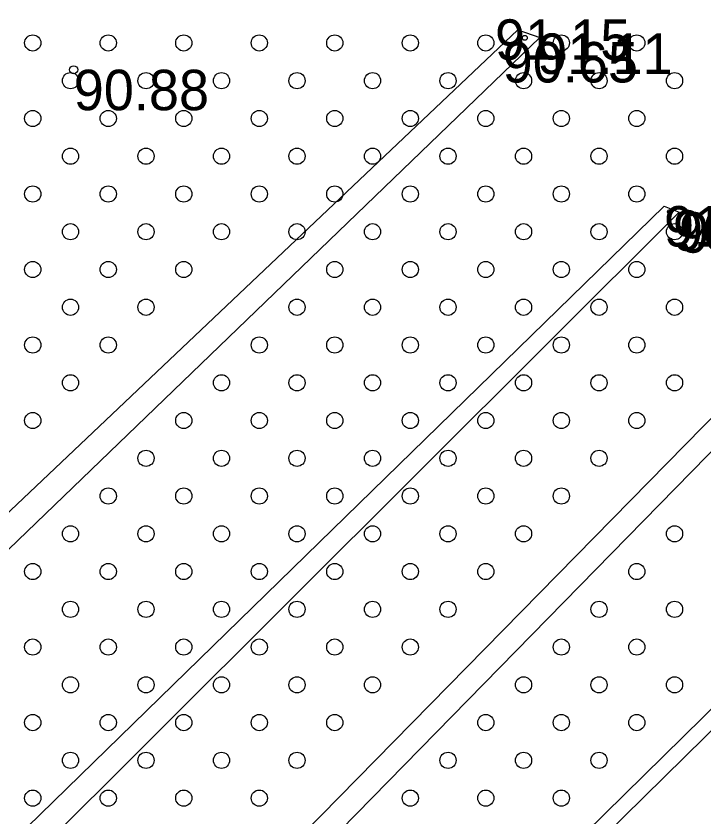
# Model space of a CAD drawing. Extents: x 316000 to 728450, y 314368 to 726000.
# Drawn here: x 725702.4 to 725766.2, y 315523.2 to 315597.5 of the extents above; entities that cross this region are included whole.
import ezdxf

# ---------------------------------------------------------------- set-up
doc = ezdxf.new("R2010")
doc.units = 0
for name, color, linetype in [('HIDG_ELEM_####_####_#', 7, 'Continuous'), ('HIDG_GRAV_####_####_#', 7, 'Continuous'), ('RELJ_AATZ_####_TKST_#', 7, 'Continuous'), ('RELJ_ELEM_####_####_#', 7, 'Continuous'), ('RELJ_NOGA_####_####_#', 7, 'Continuous'), ('TERT_ELEM_####_####_#', 7, 'Continuous')]:
    doc.layers.add(name, color=color, linetype=linetype)

msp = doc.modelspace()

# ---------------------------------------------------------------- linework, layer by layer
at = {"layer": 'HIDG_ELEM_####_####_#'}
for centre in [(725749.6236243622, 315595.47545343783), (725763.0801359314, 315579.33568528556)]:
    msp.add_circle(centre, 0.225, dxfattribs=at)
at = {"layer": 'HIDG_GRAV_####_####_#'}
for points in [[(725748.973, 315596.209), (725751.0100204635, 315595.5121681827), (725643.1476843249, 315491.6312040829), (725641.4060000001, 315494.343), (725748.973, 315596.209)], [(725762.521, 315579.879), (725763.92, 315579.31), (725655.191, 315470.892), (725652.9782202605, 315473.11112715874), (725762.521, 315579.879)], [(725774.6040000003, 315568.073), (725776.896, 315567.30999999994), (725667.3459999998, 315455.525), (725666.5099999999, 315458.031), (725774.6040000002, 315568.073)], [(725789.821, 315555.772), (725790.78, 315554.7090000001), (725668.395, 315434.39), (725667.719, 315435.797), (725789.821, 315555.772)]]:
    msp.add_lwpolyline(points, dxfattribs=at)
for points in [[(725743.944, 315631.872), (725731.1800000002, 315638.5140000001), (725730.0588248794, 315638.4860084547), (725729.0416291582, 315637.5281018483), (725728.0741186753, 315636.1890738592), (725727.1019992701, 315635.017718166), (725611.6787771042, 315529.82054677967)], [(725741.1610000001, 315628.109), (725732.013, 315633.48000000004), (725729.3674430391, 315630.93907173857), (725612.6699933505, 315527.51301727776), (725555.2138402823, 315474.3075427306)]]:
    msp.add_spline(points, degree=3, dxfattribs=at)
at = {"layer": 'RELJ_ELEM_####_####_#'}
msp.add_circle((725707.7960000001, 315592.515), 0.375, dxfattribs=at)
at = {"layer": 'RELJ_NOGA_####_####_#'}
for points in [[(725744.701, 315632.911), (725731.2122469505, 315640.0386943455), (725729.056271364, 315639.5840256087), (725728.3072907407, 315638.79600724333), (725727.6980921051, 315637.94217499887), (725727.1090350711, 315637.09598736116), (725726.4204792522, 315636.33090281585), (725610.4090988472, 315531.96836123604)], [(726259.1175937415, 315084.507430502), (726262.723, 315089.259), (726261.5614604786, 315090.83709791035), (726260.2047886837, 315092.42030988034), (726257.2926694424, 315095.5321723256), (726218.9119614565, 315136.38322796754), (726180.307, 315176.838), (726128.672, 315229.97), (726063.701, 315298.11), (725999.895, 315366.09400000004), (725937.206, 315432.091), (725876.347, 315495.232), (725810.578, 315563.08300000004), (725744.701, 315632.911)], [(725740.8620000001, 315626.984), (725732.496455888, 315631.1419358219), (725731.675729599, 315631.1475109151), (725730.9005735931, 315630.5492934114), (725730.162049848, 315629.6870659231), (725729.4512203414, 315628.90061106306), (725614.9961785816, 315525.0175506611)], [(725740.8620000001, 315626.984), (725805.544, 315558.11600000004), (725870.385, 315491.147), (725932.8030000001, 315426.796), (725994.9770000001, 315360.836), (726059.6610000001, 315292.118), (726075.7456892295, 315275.45786653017), (726092.0847165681, 315259.0432961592), (726108.4698856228, 315242.67257770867), (726124.6930000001, 315226.144), (726193.2690000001, 315154.025), (726250.0620111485, 315092.59955891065), (726256.3184263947, 315085.82961944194), (726258.824, 315084.289), (726259.1175937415, 315084.507430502)]]:
    msp.add_spline(points, degree=3, dxfattribs=at)
at = {"layer": 'TERT_ELEM_####_####_#'}
for centre in [(725704, 315595), (725711, 315595), (725718, 315595), (725725, 315595), (725732, 315595), (725739, 315595), (725746, 315595), (725753, 315595), (725760, 315595), (725707.5, 315591.5), (725714.5, 315591.5), (725721.5, 315591.5), (725728.5, 315591.5), (725735.5, 315591.5), (725742.5, 315591.5), (725749.5, 315591.5), (725756.5, 315591.5), (725763.5, 315591.5), (725704, 315588), (725711, 315588), (725718, 315588), (725725, 315588), (725732, 315588), (725739, 315588), (725746, 315588), (725753, 315588), (725760, 315588), (725707.5, 315584.5), (725714.5, 315584.5), (725721.5, 315584.5), (725728.5, 315584.5), (725735.5, 315584.5), (725742.5, 315584.5), (725749.5, 315584.5), (725756.5, 315584.5), (725763.5, 315584.5), (725704, 315581), (725711, 315581), (725718, 315581), (725725, 315581), (725732, 315581), (725739, 315581), (725746, 315581), (725753, 315581), (725760, 315581), (725707.5, 315577.5), (725714.5, 315577.5), (725721.5, 315577.5), (725728.5, 315577.5), (725735.5, 315577.5), (725742.5, 315577.5), (725749.5, 315577.5), (725756.5, 315577.5), (725763.5, 315577.5), (725704, 315574), (725711, 315574), (725718, 315574), (725732, 315574), (725739, 315574), (725746, 315574), (725753, 315574), (725760, 315574), (725707.5, 315570.5), (725714.5, 315570.5), (725728.5, 315570.5), (725735.5, 315570.5), (725742.5, 315570.5), (725749.5, 315570.5), (725756.5, 315570.5), (725763.5, 315570.5), (725704, 315567), (725711, 315567), (725725, 315567), (725732, 315567), (725739, 315567), (725746, 315567), (725753, 315567), (725760, 315567), (725707.5, 315563.5), (725721.5, 315563.5), (725728.5, 315563.5), (725735.5, 315563.5), (725742.5, 315563.5), (725749.5, 315563.5), (725756.5, 315563.5), (725763.5, 315563.5), (725704, 315560), (725718, 315560), (725725, 315560), (725732, 315560), (725739, 315560), (725746, 315560), (725753, 315560), (725760, 315560), (725714.5, 315556.5), (725721.5, 315556.5), (725728.5, 315556.5), (725735.5, 315556.5), (725742.5, 315556.5), (725749.5, 315556.5), (725756.5, 315556.5), (725711, 315553), (725718, 315553), (725725, 315553), (725732, 315553), (725739, 315553), (725746, 315553), (725753, 315553), (725707.5, 315549.5), (725714.5, 315549.5), (725721.5, 315549.5), (725728.5, 315549.5), (725735.5, 315549.5), (725742.5, 315549.5), (725749.5, 315549.5), (725763.5, 315549.5), (725704, 315546), (725711, 315546), (725718, 315546), (725725, 315546), (725732, 315546), (725739, 315546), (725746, 315546), (725760, 315546), (725707.5, 315542.5), (725714.5, 315542.5), (725721.5, 315542.5), (725728.5, 315542.5), (725735.5, 315542.5), (725742.5, 315542.5), (725756.5, 315542.5), (725763.5, 315542.5), (725704, 315539), (725711, 315539), (725718, 315539), (725725, 315539), (725732, 315539), (725739, 315539), (725753, 315539), (725760, 315539), (725707.5, 315535.5), (725714.5, 315535.5), (725721.5, 315535.5), (725728.5, 315535.5), (725735.5, 315535.5), (725749.5, 315535.5), (725756.5, 315535.5), (725763.5, 315535.5), (725704, 315532), (725711, 315532), (725718, 315532), (725725, 315532), (725732, 315532), (725746, 315532), (725753, 315532), (725760, 315532), (725707.5, 315528.5), (725714.5, 315528.5), (725721.5, 315528.5), (725728.5, 315528.5), (725742.5, 315528.5), (725749.5, 315528.5), (725756.5, 315528.5), (725704, 315525), (725711, 315525), (725718, 315525), (725725, 315525), (725739, 315525), (725746, 315525), (725753, 315525)]:
    msp.add_circle(centre, 0.75, dxfattribs=at)

# ---------------------------------------------------------------- texts
at = {"layer": 'RELJ_AATZ_####_TKST_#'}
for s, p in [('91.15', (725746.853, 315593.436)), ('91.11', (725750.7740000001, 315592.13)), ('90.65', (725747.56, 315591.337)), ('90.88', (725707.7960000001, 315588.765)), ('91.13', (725762.5210000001, 315576.129)), ('90.39', (725763.3450000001, 315575.735)), ('91.12', (725763.92, 315575.56))]:
    msp.add_text(s, height=3.75, dxfattribs=at).set_placement(p)

doc.saveas('drawing.dxf')
